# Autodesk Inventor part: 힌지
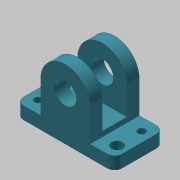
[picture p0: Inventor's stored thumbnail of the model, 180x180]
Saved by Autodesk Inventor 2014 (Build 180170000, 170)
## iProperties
Created: 2019-09
Part Number: 힌지
Material: 알루미늄 6061
Document SubType Name: Modeling
Designer: mduedu
Density: 1 g/cm^3
Appearance: 커뎃 파란색
Author: mduedu
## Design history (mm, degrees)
sketch "스케치1"
  geometry: L1 (-20, 0)-(20, 0); L2 (20, 0)-(20, 5); L3 (-20, 5)-(-20, 0); L4 (10, 5)-(10, 18); L5 (-10, 18)-(-10, 5); L6 (20, 5)-(10, 5); L7 (-10, 5)-(-20, 5); C1 r 4.5 at (0, 18); A1 r 10 centre (0, 18) between (10, 18) and (-10, 18); 2 further points
  constraints: 14 end point, 4 parallel, 2 centre point, 2 coincident, 2 point on circle, 2 tangent, 1 collinear, 1 horizontal, 1 midpoint, 1 perpendicular, 1 vertical, 1 vertical alignment
  dimensions: "d0" = 40 distance of L1.start L1.end; "d2" = 20 distance between parallel lines of L4 L5; "d3" = 18 distance from line of L1 A1.centre; "d4" = 5 distance of L1.end L2.end; "d5" = 9 diameter of C1
extrude "돌출1" new body sketch "스케치1" stored distance "d6" = 20; taper "d7" = 0 deg
sketch "스케치2"
  geometry: L1 (7, 5)-(37, 5); L2 (37, 5)-(37, -5); L3 (37, -5)-(7, -5); L4 (7, -5)-(7, 5); L5 (0, 10)-(0, -10) reference; 2 further points
  constraints: 8 end point, 2 parallel, 1 horizontal, 1 horizontal alignment, 1 midpoint, 1 perpendicular
  dimensions: "d8" = 7 distance between parallel lines of L5 L4; "d9" = 10 distance of L1.end L2.end; "d10" = 30 distance of L2.end L3.end
extrude "돌출2" cut sketch "스케치2" stored distance "d11" = 20; taper "d12" = 0 deg
sketch "스케치3"
  geometry: 3 further points
  dimensions: "d13" = 16 horizontal distance of point (6, 15) point (-10, 10); "d14" = 32 horizontal distance of point (-26, 5) point (6, 15); "d15" = 5 vertical distance of point (6, 15) point (-10, 10); "d16" = 10 vertical distance of point (-26, 5) point (6, 15)
hole "구멍1" sketch "스케치3" at (6, 15), (-26, 5) diameter "d17" = 3; stored, may be unused: countersink angle "d21" = 90 deg, drill point angle "d23" = 118 deg; dims "d18" = 6, "d19" = 4, "d20" = 2, "d22" = 8
sketch "스케치4"
  geometry: C1 r 1.5 at (6, 15) reference; C2 r 1.5 at (-26, 5) reference; 3 further points
  constraints: 2 horizontal alignment, 2 vertical alignment
hole "구멍2" sketch "스케치4" at (-26, 15), (6, 5) diameter "d24" = 4.5; stored, may be unused: countersink angle "d28" = 90 deg, drill point angle "d30" = 118 deg; dims "d25" = 6, "d26" = 4, "d27" = 2, "d29" = 8
fillet "모깎기1" dims "d31" = 3
node "솔리드1"
